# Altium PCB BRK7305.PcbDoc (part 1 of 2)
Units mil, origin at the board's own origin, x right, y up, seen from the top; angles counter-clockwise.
Board outline 4724.41 x 3149.61 mil, 4 copper layers (L1-TOP, L2-GND, L3-PWR, L4-BOT), stack 60.267 mil thick; 97 components, 177 nets, 610 pads, 294 vias.
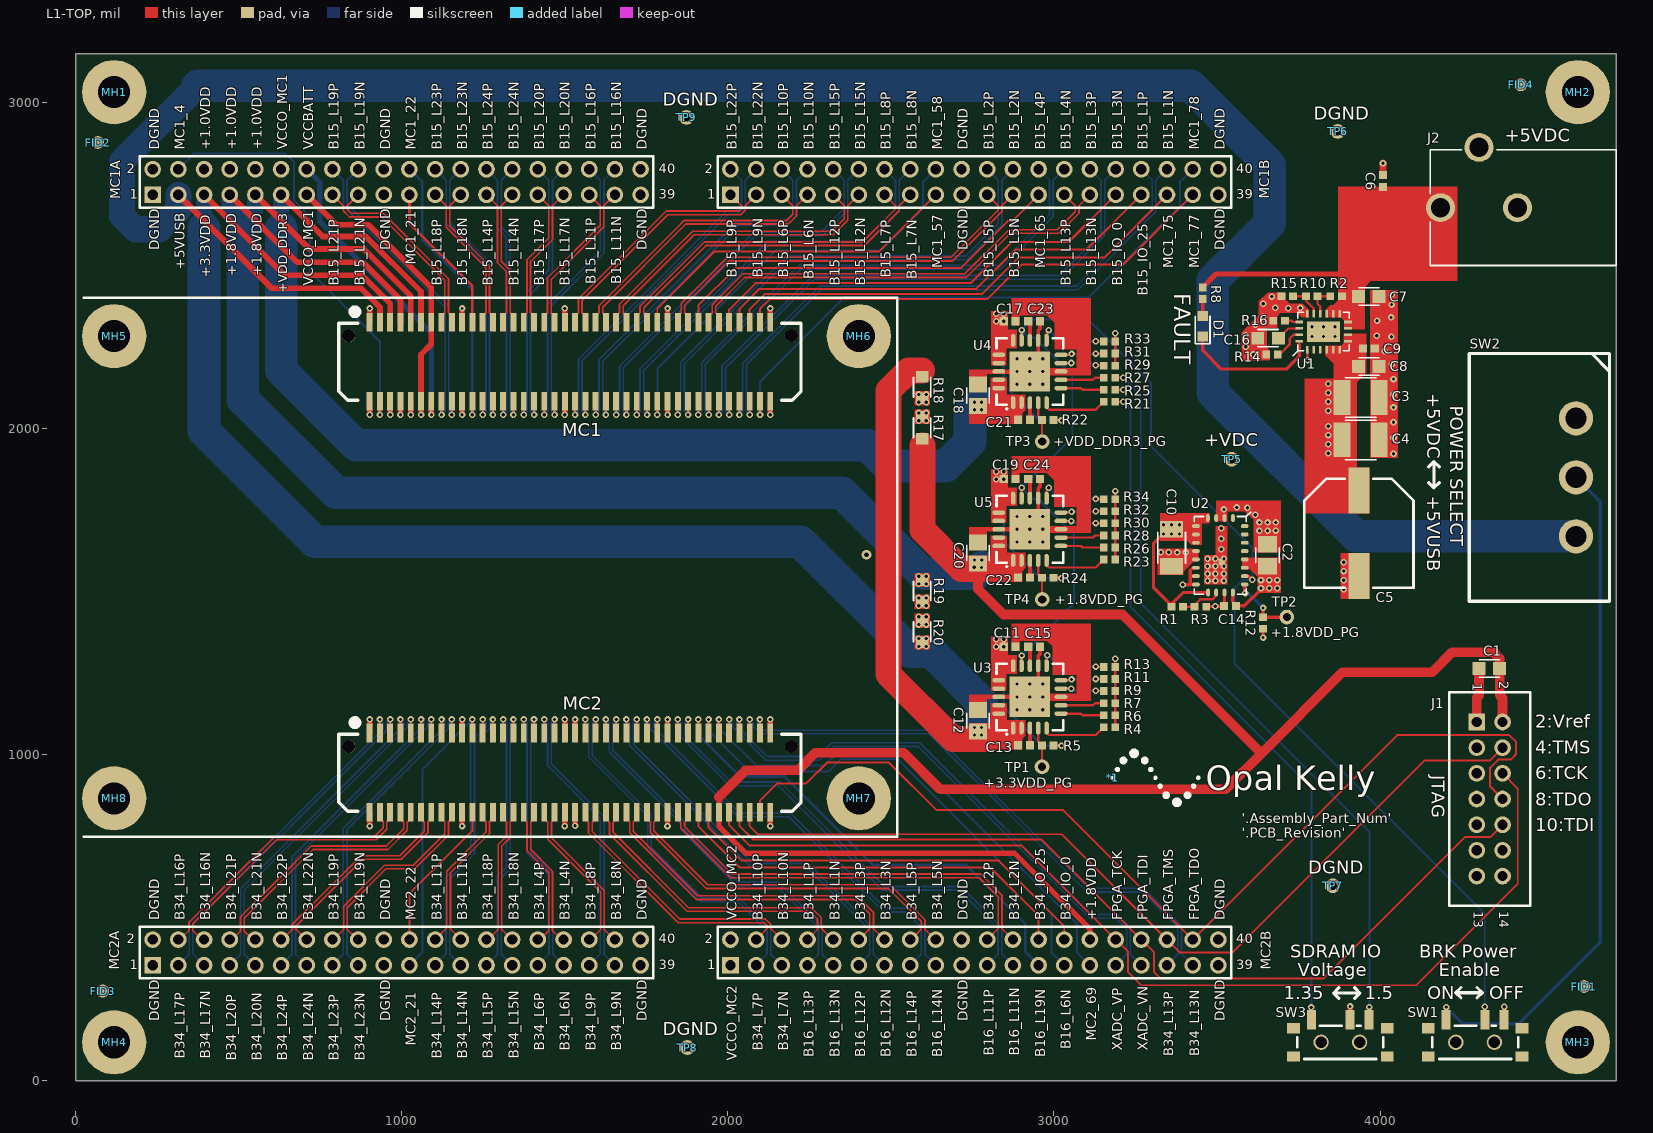
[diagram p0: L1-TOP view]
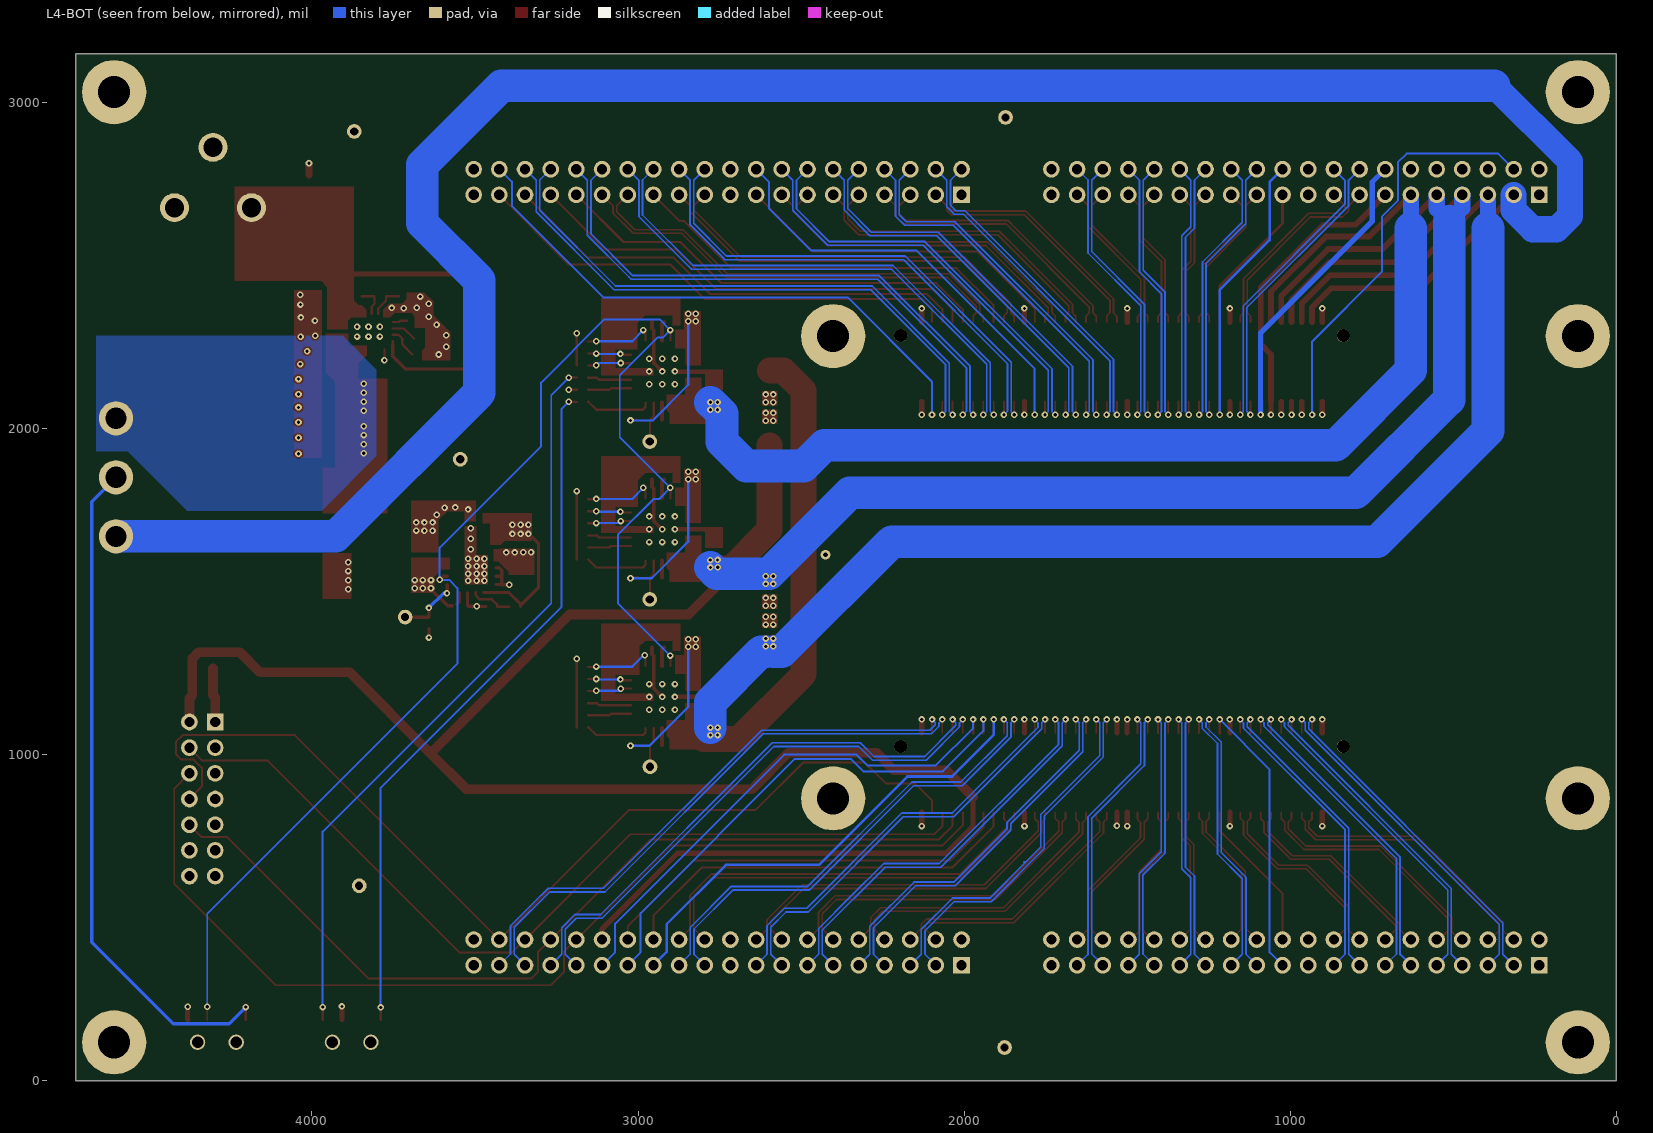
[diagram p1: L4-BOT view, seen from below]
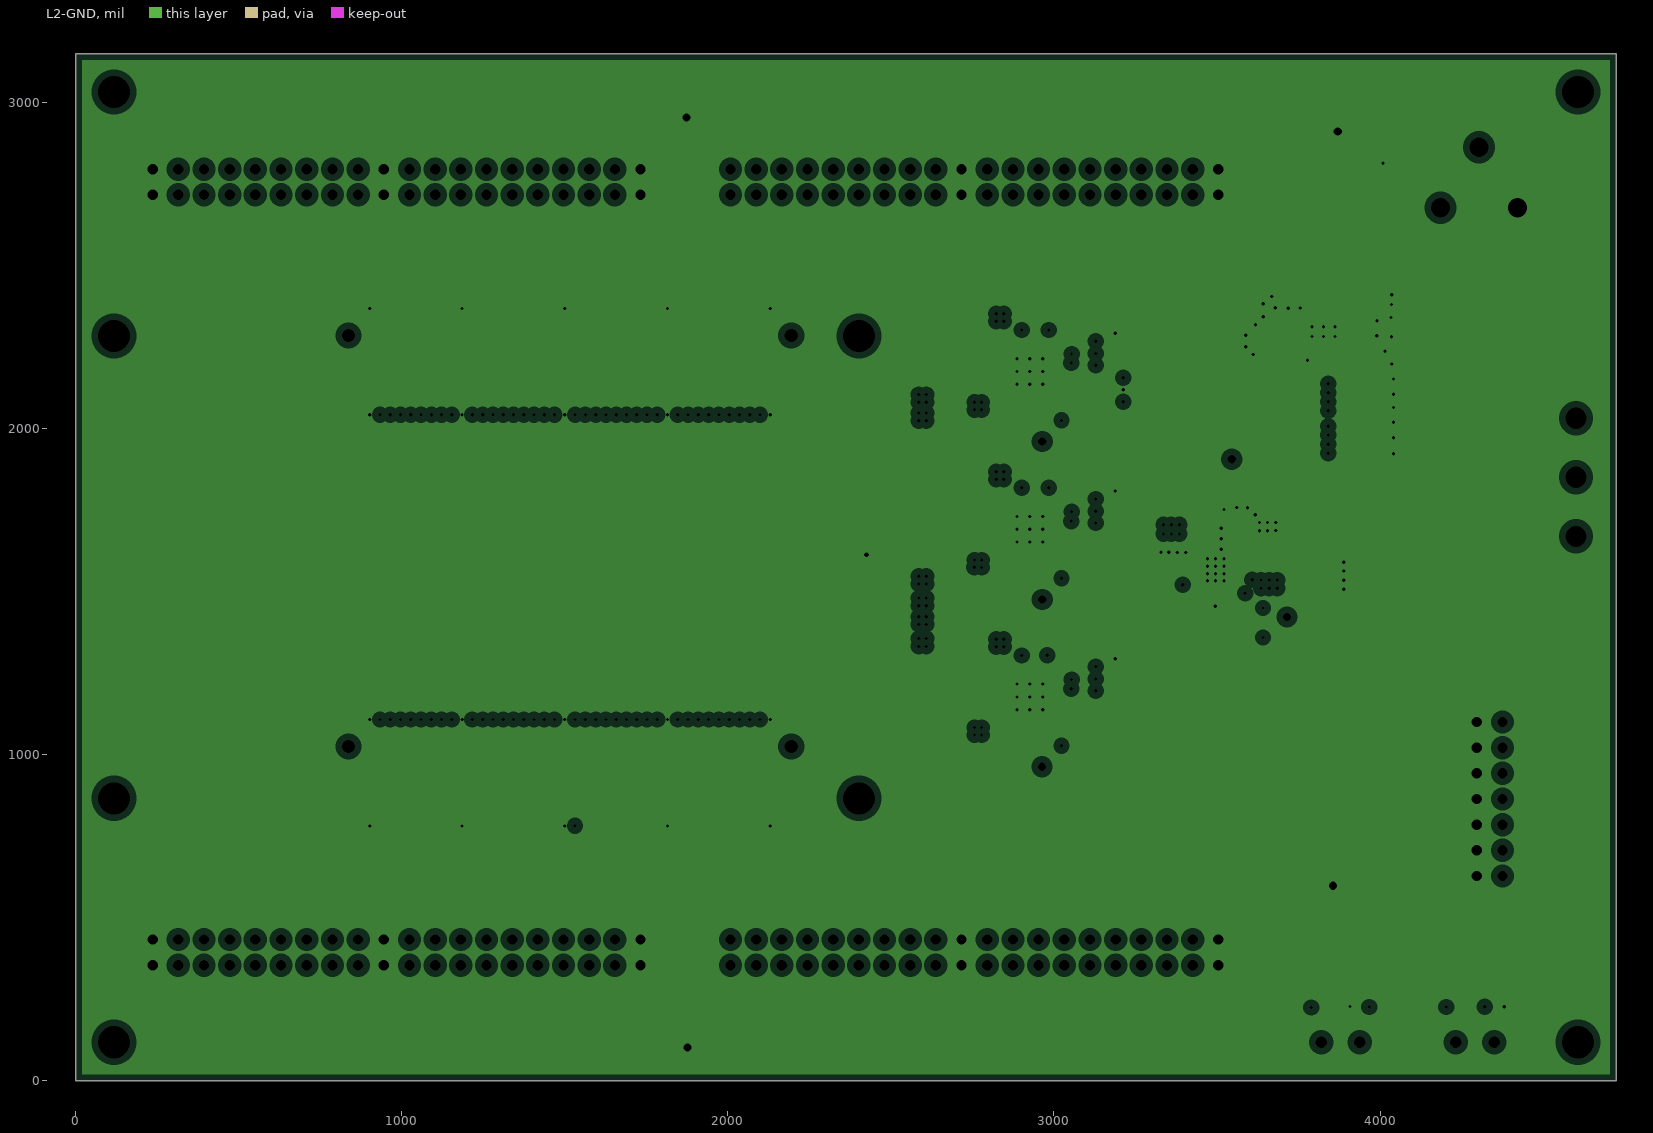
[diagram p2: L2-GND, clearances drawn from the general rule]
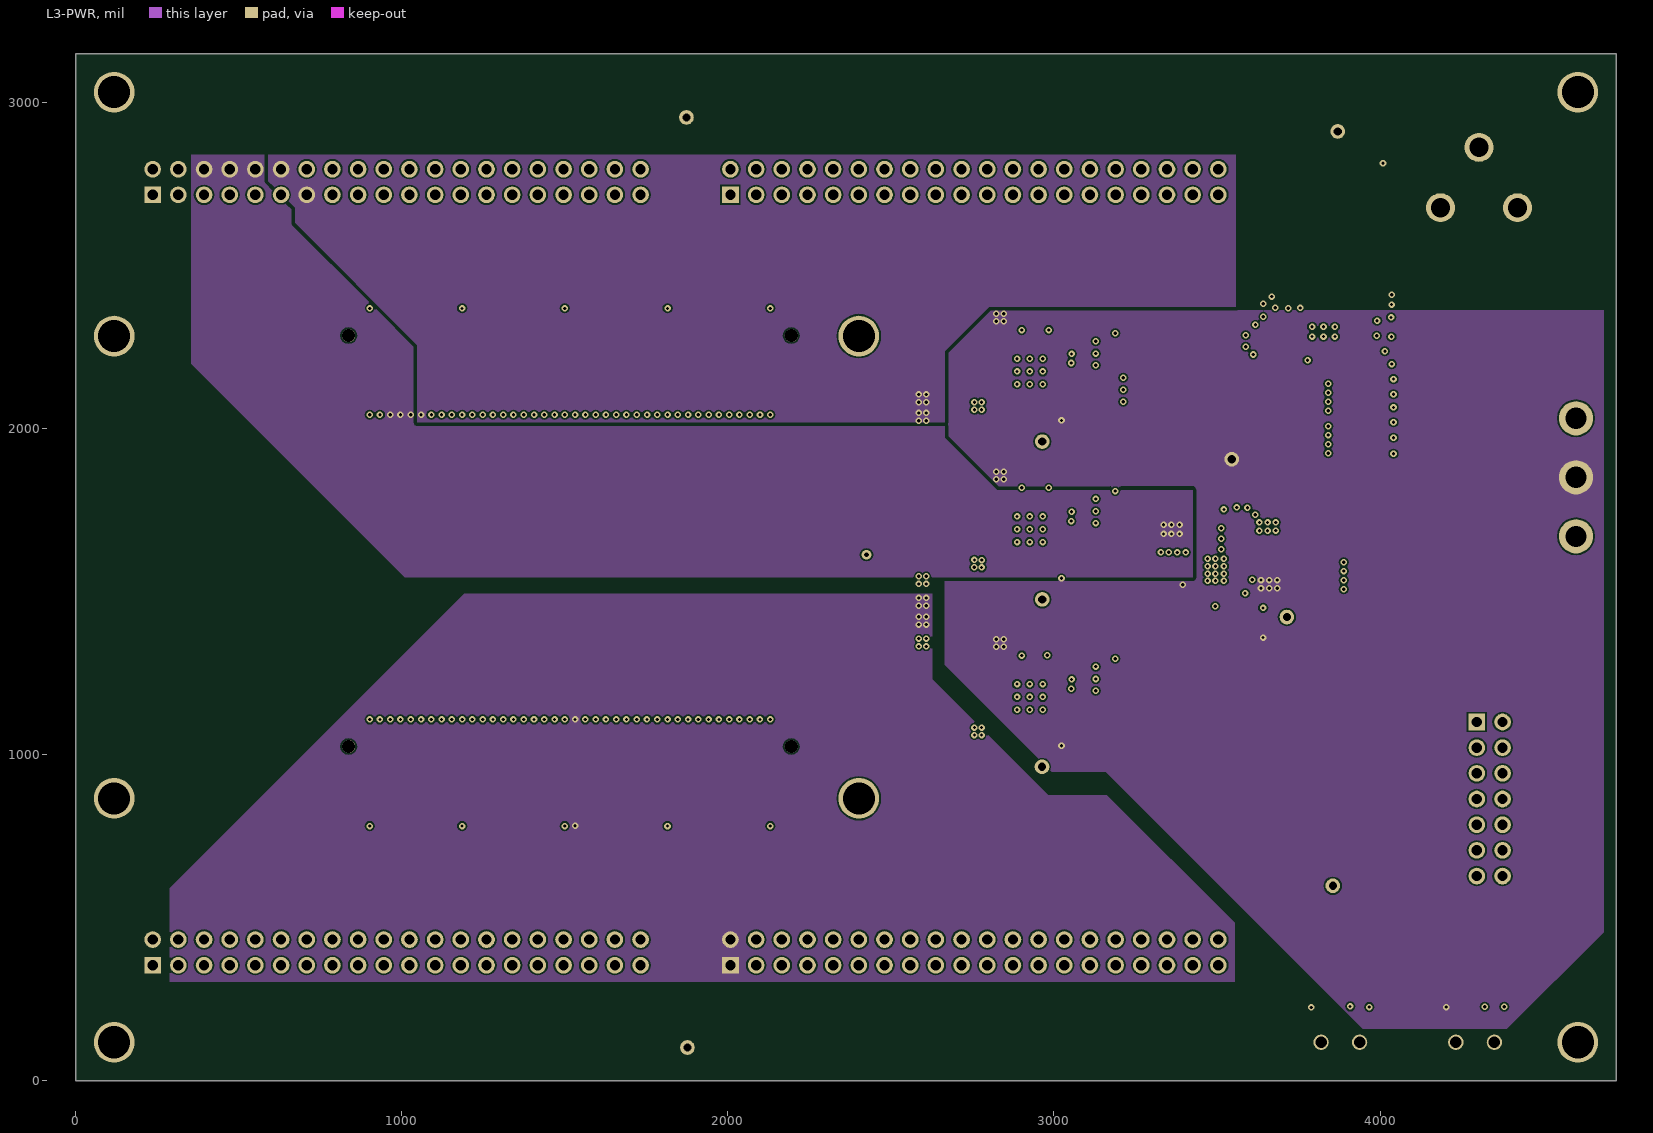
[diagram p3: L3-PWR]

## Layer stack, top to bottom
Top Solder: solder mask 0.4, Solder Resist, Dk 3.5
L1-TOP: signal copper 1.4
Dielectric1: prepreg 5.08, IT180A, Dk 4.2
L2-GND: plane copper 1.4, net DGND
Dielectric 2: core 44.49, IT180A, Dk 4.2
L3-PWR: signal copper 1.417
Dielectric 3: prepreg 5.08, IT180A, Dk 4.2
L4-BOT: signal copper 1.4
Bottom Solder: solder mask 0.4, Solder Resist, Dk 3.5

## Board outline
0,0 4724.41,0 4724.41,3149.61 0,3149.61

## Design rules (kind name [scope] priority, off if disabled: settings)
Clearance Fiducial [All vs ((Not PadIsPlated) And (HoleSize = 0))] p1: gap=25 ignorepadtopadclearanceinfootprint=FALSE except(0: Arc-Hole Track-Hole SMDPad-Hole THPad-Hole Via-Hole Fill-Hole Poly-Hole Region-Hole Text-Hole)
Clearance [All] p2: gap=5 ignorepadtopadclearanceinfootprint=FALSE except(0: Arc-Hole Track-Hole SMDPad-Hole THPad-Hole Via-Hole Fill-Hole Poly-Hole Region-Hole Text-Hole; 12: Fill-Fill Fill-Poly Fill-Region Poly-Poly Poly-Region Region-Region)
DiffPairsRouting okxDiffRouting100ohm [All] p1: maxlimit=10 minlimit=6 mostfreqgap=10 toplayer_maxgap=6 toplayer_prefgap=6 toplayer_minwidth=5.25 toplayer_maxwidth=5.25 toplayer_prefwidth=5.25 midlayer1_mingap=10 midlayer1_minwidth=15 midlayer1_maxwidth=15 midlayer1_prefwidth=15 bottomlayer_maxgap=6 bottomlayer_prefgap=6 bottomlayer_minwidth=5.25 bottomlayer_maxwidth=5.25 bottomlayer_prefwidth=5.25 maxuncoupledlength=500
FabricationTestPointUsage TestPointUsage [All] p1: valid=0 allowmultiple=FALSE
FabricationTestpoint Testpoint [All] p1: side=3 testpointundercomponent=TRUE minsize=40 maxsize=100 preferedsize=60 minholesize=0 maxholesize=40 preferedholesize=32 testpointgrid=1 allowsidetop=TRUE allowsidebottom=TRUE usegrid=TRUE gridtolerance=0.01
HoleSize [All] p1: absolutevalues=TRUE maxlimit=100 minlimit=8 maxpercent=80.000 minpercent=20.000
MinimumSolderMaskSliver [All] p1: minsoldermaskwidth=3
PlaneClearance [All] p1: clearance=20
PlaneConnect [All] p1: planeconnectstyle=Direct reliefexpansion=20 reliefentries=4 reliefconductorwidth=10 reliefairgap=10
PolygonConnect "Via Connect" [IsVia] p1: connectstyle=Direct reliefconductorwidth=10 reliefentries=4 polygonreliefangle="90 Angle" airgapwidth=10
PolygonConnect [All] p2: connectstyle=Direct reliefconductorwidth=10 reliefentries=4 polygonreliefangle="90 Angle" airgapwidth=10
RoutingVias [All] p1: holewidth=8 width=16 viastyle="Through Hole" minholewidth=8 minwidth=16 maxholewidth=25 maxwidth=50
SilkToSilkClearance [All] p1: silktosilkclearance=0.1
SilkToSolderMaskClearance [IsPad] p1: minsilkscreentomaskgap=2 clearancetoexposedcopper=TRUE
SolderMaskExpansion [All] p1: expansion=3
Width okWidth [All] p1: maxlimit=200 minlimit=5 preferedwidth=5 minimp=50.000000 maximp=50.000000 favimp=50.000000
21 further rules are at their usual default settings.

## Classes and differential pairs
differential pair DP_XADC: +XADC_VP -XADC_VN
differential pair DP_B34_L24: +B34_L24P -B34_L24N
differential pair DP_B34_L23: +B34_L23P -B34_L23N
differential pair DP_B34_L22: +B34_L22P -B34_L22N
differential pair DP_B34_L21: +B34_L21P -B34_L21N
differential pair DP_B34_L20: +B34_L20P -B34_L20N
differential pair DP_B34_L19: +B34_L19P -B34_L19N
differential pair DP_B34_L18: +B34_L18P -B34_L18N
differential pair DP_B34_L17: +B34_L17P -B34_L17N
differential pair DP_B34_L16: +B34_L16P -B34_L16N
differential pair DP_B34_L15: +B34_L15P -B34_L15N
differential pair DP_B34_L14: +B34_L14P -B34_L14N
differential pair DP_B34_L13_MRCC: +B34_L13P_MRCC -B34_L13N_MRCC
differential pair DP_B34_L11: +B34_L11P -B34_L11N
differential pair DP_B34_L10: +B34_L10P -B34_L10N
differential pair DP_B34_L9: +B34_L9P -B34_L9N
differential pair DP_B34_L8: +B34_L8P -B34_L8N
differential pair DP_B34_L7: +B34_L7P -B34_L7N
differential pair DP_B34_L6: +B34_L6P -B34_L6N
differential pair DP_B34_L5: +B34_L5P -B34_L5N
differential pair DP_B34_L4: +B34_L4P -B34_L4N
differential pair DP_B34_L3: +B34_L3P -B34_L3N
differential pair DP_B34_L2: +B34_L2P -B34_L2N
differential pair DP_B34_L1: +B34_L1P -B34_L1N
differential pair DP_B16_L14: +B16_L14P -B16_L14N
differential pair DP_B16_L13: +B16_L13P -B16_L13N
differential pair DP_B16_L12: +B16_L12P -B16_L12N
differential pair DP_B16_L11: +B16_L11P -B16_L11N
differential pair DP_B15_L24: +B15_L24P -B15_L24N
differential pair DP_B15_L23: +B15_L23P -B15_L23N
differential pair DP_B15_L22: +B15_L22P -B15_L22N
differential pair DP_B15_L21: +B15_L21P -B15_L21N
differential pair DP_B15_L20: +B15_L20P -B15_L20N
differential pair DP_B15_L19: +B15_L19P -B15_L19N
differential pair DP_B15_L18: +B15_L18P -B15_L18N
differential pair DP_B15_L17: +B15_L17P -B15_L17N
differential pair DP_B15_L16: +B15_L16P -B15_L16N
differential pair DP_B15_L15: +B15_L15P -B15_L15N
differential pair DP_B15_L14: +B15_L14P -B15_L14N
differential pair DP_B15_L13_MRCC: +B15_L13P_MRCC -B15_L13N_MRCC
differential pair DP_B15_L12_MRCC: +B15_L12P_MRCC -B15_L12N_MRCC
differential pair DP_B15_L11: +B15_L11P -B15_L11N
differential pair DP_B15_L10: +B15_L10P -B15_L10N
differential pair DP_B15_L9: +B15_L9P -B15_L9N
differential pair DP_B15_L8: +B15_L8P -B15_L8N
differential pair DP_B15_L7: +B15_L7P -B15_L7N
differential pair DP_B15_L6: +B15_L6P -B15_L6N
differential pair DP_B15_L5: +B15_L5P -B15_L5N
differential pair DP_B15_L4: +B15_L4P -B15_L4N
differential pair DP_B15_L3: +B15_L3P -B15_L3N
differential pair DP_B15_L2: +B15_L2P -B15_L2N
differential pair DP_B15_L1: +B15_L1P -B15_L1N

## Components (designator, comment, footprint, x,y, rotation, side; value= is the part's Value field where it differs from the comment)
*1 "Opal Kelly Logo" okLogo-23x5 3180,929 r0 top
C1 "C0603C104K4RACTU" CAPC1608N 4335,1264 r0 top value="0.1 u"
C2 "LMK212BJ106KG-T" CAPC2012N 3654.73,1611.44 r270 top locked value=10u
C3 "GRM32ER61C476KE15K" CAPC3225N 3940.41,2095.14 r0 top value="47 u"
C4 "GRM32ER61C476KE15K" CAPC3225N 3940.41,1965.14 r0 top value="47 u"
C5 "6SVPS220M" CAPAE9083X70N 3935,1679 r270 top value=220u
C6 "TMK105BJ104KV-F" CAPC1005X06N 4009,2759 r270 top value="0.1 u"
C7 "C0603C104K4RACTU" CAPC1608N 3965.41,2405.14 r180 top value="0.1 u"
C8 "C0603C104K4RACTU" CAPC1608N 3965.41,2190.14 r180 top value="0.1 u"
C9 "LMK105BJ105KV-F" CAPC1005X06N 3965.41,2245.14 r180 top value=1u
C10 "JMK316BJ476ML-T" CAPC3216N 3360.73,1634.44 r90 top locked value="47 u"
C11 "LMK105BJ105KV-F" CAPC1005X06N 2864,1331 r180 top value=1u
C12 "LMK212BJ106KG-T" CAPC2012X14N 2767,1104 r270 top value=10u
C13 "C0402C221J5GACTU" CAPC1005X06N 2908,1029 r180 top value="220 p"
C14 "LMK105BJ105KV-F" CAPC1005X06N 3539.73,1455.44 r0 top value=1u
C15 "C0402C103K4RACTU" CAPC1005X06N 2939,1331 r180 top value="0.01 u"
C16 "C0603C104K4RACTU" CAPC1608N 3656.41,2276.94 r0 top value="0.1 u"
C17 "LMK105BJ105KV-F" CAPC1005X06N 2864,2329 r180 top value=1u
C18 "LMK212BJ106KG-T" CAPC2012X14N 2767,2102 r270 top value=10u
C19 "LMK105BJ105KV-F" CAPC1005X06N 2864,1845.18 r180 top value=1u
C20 "LMK212BJ106KG-T" CAPC2012X14N 2767,1618.18 r270 top value=10u
C21 "C0402C221J5GACTU" CAPC1005X06N 2908,2027 r180 top value="220 p"
C22 "C0402C221J5GACTU" CAPC1005X06N 2908,1543.18 r180 top value="220 p"
C23 "C0402C103K4RACTU" CAPC1005X06N 2939,2329 r180 top value="0.01 u"
C24 "C0402C103K4RACTU" CAPC1005X06N 2939,1845.18 r180 top value="0.01 u"
D1 "FAULT" DIALIGHT-598-0603 3455.76,2313.49 r90 top
FID1 "FIDUCIAL" FID1MM/2MM-SS 4625,289 r90 top
FID2 "FIDUCIAL" FID1MM/2MM-SS 68,2877 r90 top
FID3 "FIDUCIAL" FID1MM/2MM-SS 83,275 r90 top
FID4 "FIDUCIAL" FID1MM/2MM-SS 4431,3054 r90 top
J1 "87831-1420" XILINX-JTAG 4336,864 r270 top
J2 "PJ-102AH" CUI-PJ102A 4724.41,2677.17 r90 top
MC1 "BTE-040-01-F-D-A" BTE-040 1515.75,2204.73 r0 top locked
MC1A "0877584016" HDR2X20-2MM 984.25,2755.91 r0 top locked
MC1B "0877584016" HDR2X20-2MM 2755.91,2755.91 r0 top locked
MC2 "BTE-040-01-F-D-A" BTE-040 1515.75,944.88 r0 top locked
MC2A "0877584016" HDR2X20-2MM 984.25,393.7 r0 top locked
MC2B "0877584016" HDR2X20-2MM 2755.91,393.7 r0 top locked
MH1 "MTG" MTG-2.5/5.0-PTH 118.11,3031.5 r0 top
MH2 "MTG" MTG-2.5/5.0-PTH 4606.3,3031.5 r0 top
MH3 "MTG" MTG-2.5/5.0-PTH 4606.3,118.11 r0 top
MH4 "MTG" MTG-2.5/5.0-PTH 118.11,118.11 r0 top
MH5 "MTG" MTG-2.5/5.0-PTH 118.11,2283.47 r0 top
MH6 "MTG" MTG-2.5/5.0-PTH 2401.58,2283.47 r0 top
MH7 "MTG" MTG-2.5/5.0-PTH 2401.58,866.14 r0 top
MH8 "MTG" MTG-2.5/5.0-PTH 118.11,866.14 r0 top
R1 "CRCW0402340KFKED" RESC1005X06N 3377.72,1454 r180 top value="340 k"
R2 "CRCW0402105KFKED" RESC1005X06N 3865.21,2405.84 r0 top value="105 k"
R3 "CRCW0402511KFKED" RESC1005X06N 3448.72,1454 r180 top value="511 k"
R4 "CRCW04020000Z0ED" RESC1005X06N 3170,1084 r180 top value=0
R5 "CRCW040210K0JNED" RESC1005X06N 2981,1028 r0 top value="10 k"
R6 "CRCW04020000Z0ED" RESC1005X06N 3170,1121 r180 top value=0
R7 "CRCW04020000Z0ED" RESC1005X06N 3170,1158 r180 top value=0
R8 "CRCW0402200RFKED" RESC1005X06N 3456,2415 r90 top value=200
R9 "CRCW04020000Z0ED" RESC1005X06N 3170,1195 r180 top value=0
R10 "CRCW040210K0JNED" RESC1005X06N 3790.21,2405.84 r0 top value="10 k"
R11 "CRCW04020000Z0ED" RESC1005X06N 3170,1232 r180 top value=0
R12 "CRCW040210K0JNED" RESC1005X06N 3641,1404 r270 top value="10 k"
R13 "CRCW04020000Z0ED" RESC1005X06N 3170,1269 r180 top value=0
R14 "CRCW040224K9FKED" RESC1005X06N 3668.41,2227.14 r0 top value="24.9 k"
R15 "CRCW040224K9FKED" RESC1005X06N 3715.21,2405.84 r0 top value="24.9 k"
R16 "CRCW040216K9FKED" RESC1005X06N 3690.41,2330.14 r0 top value="16.9 k"
R17 "CRCW06030000Z0EA" RESC1608N 2596,2002.54 r90 top value=0
R18 "CRCW06030000Z0EA" RESC1608N 2596,2126 r90 top value=0
R19 "CRCW06030000Z0EA" RESC1608N 2596,1502 r270 top value=0
R20 "CRCW06030000Z0EA" RESC1608N 2596,1377.54 r270 top value=0
R21 "CRCW04020000Z0ED" RESC1005X06N 3170,2082 r180 top value=0
R22 "CRCW040210K0JNED" RESC1005X06N 2981,2026 r0 top value="10 k"
R23 "CRCW04020000Z0ED" RESC1005X06N 3170,1598.18 r180 top value=0
R24 "CRCW040210K0JNED" RESC1005X06N 2981,1542.18 r0 top value="10 k"
R25 "CRCW04020000Z0ED" RESC1005X06N 3170,2119 r180 top value=0
R26 "CRCW04020000Z0ED" RESC1005X06N 3170,1635.18 r180 top value=0
R27 "CRCW04020000Z0ED" RESC1005X06N 3170,2156 r180 top value=0
R28 "CRCW04020000Z0ED" RESC1005X06N 3170,1672.18 r180 top value=0
R29 "CRCW04020000Z0ED" RESC1005X06N 3170,2193 r180 top value=0
R30 "CRCW04020000Z0ED" RESC1005X06N 3170,1709.18 r180 top value=0
R31 "CRCW04020000Z0ED" RESC1005X06N 3170,2230 r180 top value=0
R32 "CRCW04020000Z0ED" RESC1005X06N 3170,1746.18 r180 top value=0
R33 "CRCW04020000Z0ED" RESC1005X06N 3170,2267 r180 top value=0
R34 "CRCW04020000Z0ED" RESC1005X06N 3170,1783.18 r180 top value=0
SW1 "SSSS811101" SSSS811101 4291.34,118.11 r0 top
SW2 "L102011MS02Q" L102011MS 4488.19,1850.39 r180 top
SW3 "SSSS811101" SSSS811101 3877.95,118.11 r0 top
TP1 "+3.3VDD_PG" TP-PTH-25/45 2963.28,962.72 r180 top
TP2 "+1.8VDD_PG" TP-PTH-25/45 3714,1422 r270 top
TP3 "+VDD_DDR3_PG" TP-PTH-25/45 2964,1960 r90 top
TP4 "+1.8VDD_PG" TP-PTH-25/45 2964,1476.18 r180 top
TP5 "+VDC" TP-PTH-25/45 3545,1906 r90 top
TP6 "DGND" TP-PTH-25/45 3870,2911 r90 top
TP7 "DGND" TP-PTH-25/45 3855,598 r90 top
TP8 "DGND" TP-PTH-25/45 1876,102 r90 top
TP9 "DGND" TP-PTH-25/45 1873,2954 r90 top
U1 "TPS25940A" TPS25940 3826.41,2297.14 r0 top
U2 "EN5322" EN5322QI 3510.08,1611.44 r270 top
U3 "TPS7A7100RGWT" S-PVQN-N20 2926,1177 r90 top
U4 "TPS7A7100RGWT" S-PVQN-N20 2926,2175 r90 top
U5 "TPS7A7100RGWT" S-PVQN-N20 2926,1691.18 r90 top

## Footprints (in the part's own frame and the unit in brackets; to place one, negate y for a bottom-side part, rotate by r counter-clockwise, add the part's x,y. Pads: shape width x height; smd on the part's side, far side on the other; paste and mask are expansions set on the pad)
BTE-040 [mm] "0.8mm Samtech socket"
  rect 0.46x1.45 smd: 1(-15.6,3.085) 2(-15.6,-3.085) 3(-14.8,3.085) 4(-14.8,-3.085) 5(-14,3.085) 6(-14,-3.085) 7(-13.2,3.085) 8(-13.2,-3.085) 9(-12.4,3.085) 10(-12.4,-3.085) 11(-11.6,3.085) 12(-11.6,-3.085) 13(-10.8,3.085) 14(-10.8,-3.085) 15(-10,3.085) 16(-10,-3.085) 17(-9.2,3.085) 18(-9.2,-3.085) 19(-8.4,3.085) 20(-8.4,-3.085) 21(-7.6,3.085) 22(-7.6,-3.085) 23(-6.8,3.085) 24(-6.8,-3.085) 25(-6,3.085) 26(-6,-3.085) 27(-5.2,3.085) 28(-5.2,-3.085) 29(-4.4,3.085) 30(-4.4,-3.085) 31(-3.6,3.085) 32(-3.6,-3.085) 33(-2.8,3.085) 34(-2.8,-3.085) 35(-2,3.085) 36(-2,-3.085) 37(-1.2,3.085) 38(-1.2,-3.085) 39(-0.4,3.085) 40(-0.4,-3.085) 41(0.4,3.085) 42(0.4,-3.085) 43(1.2,3.085) 44(1.2,-3.085) 45(2,3.085) 46(2,-3.085) 47(2.8,3.085) 48(2.8,-3.085) 49(3.6,3.085) 50(3.6,-3.085) 51(4.4,3.085) 52(4.4,-3.085) 53(5.2,3.085) 54(5.2,-3.085) 55(6,3.085) 56(6,-3.085) 57(6.8,3.085) 58(6.8,-3.085) 59(7.6,3.085) 60(7.6,-3.085) 61(8.4,3.085) 62(8.4,-3.085) 63(9.2,3.085) 64(9.2,-3.085) 65(10,3.085) 66(10,-3.085) 67(10.8,3.085) 68(10.8,-3.085) 69(11.6,3.085) 70(11.6,-3.085) 71(12.4,3.085) 72(12.4,-3.085) 73(13.2,3.085) 74(13.2,-3.085) 75(14,3.085) 76(14,-3.085) 77(14.8,3.085) 78(14.8,-3.085) 79(15.6,3.085) 80(15.6,-3.085)
  round 1.02 hole 1.02: 81(-17.235,2.035) 82(17.235,2.035)
  silkscreen extent -18,-3 18,4.15
CAPAE9083X70N [mm] "Aluminum Electrolytic Capacitor, Body 8.30x8.30x7.00mm, IPC Medium Density"
  rect 3.6x1.65 smd: 1(-3.325,0) 2(3.325,0)
  silkscreen extent -4.25,-4.25 4.25,4.25, body extent -4.25,-4.25 4.25,4.25, height 7
CAPC1005X06N [mm] "Chip Capacitor, 2-Leads, Body 1.00x0.50mm, IPC Medium Density"
  rect 0.64x0.64 smd: 1(-0.46,0) 2(0.46,0)
  body extent -0.55,-0.3 0.55,0.3, height 0.6
CAPC1608N [mm] "Chip Capacitor, Body 1.6x0.8mm, IPC Medium Density"
  rect 1x1 smd: 1(-0.8,0) 2(0.8,0)
  silkscreen extent -0.8,-0.68 0.8,0.68, body extent -0.87,-0.48 0.87,0.48, height 0.85
CAPC2012N [mm] "Chip Capacitor, Body 2.0x1.3mm, IPC Medium Density"
  rect 1.3x1.5 smd: 1(-0.85,0) 2(0.85,0)
  silkscreen extent -0.6,-0.93 0.6,0.93, body extent -1.1,-0.72 1.1,0.72, height 1.1
CAPC2012X14N [mm] "Chip Capacitor, 2-Leads, Body 2.00x1.25mm, IPC Medium Density"
  rect 1.25x1.4 smd: 1(-0.825,0) 2(0.825,0)
  silkscreen extent -0.6,-0.88 0.6,0.88, body extent -1.05,-0.67 1.05,0.67, height 1.4
CAPC3216N [mm] "Chip Capacitor, Body 3.2x1.6mm, IPC Medium Density"
  rect 1.3x1.8 smd: 1(-1.45,0) 2(1.45,0)
  silkscreen extent -1.2,-1.08 1.2,1.08, body extent -1.7,-0.9 1.7,0.9, height 1.35
CAPC3225N [mm] "Chip Capacitor, Body 3.2x2.5mm, IPC Medium Density"
  rect 1.3x2.7 smd: 1(-1.45,0) 2(1.45,0)
  silkscreen extent -1.2,-1.53 1.2,1.53, body extent -1.7,-1.35 1.7,1.35, height 1.35
CUI-PJ102A [mm] "2.1mm/5.5mm DC power jack"
  round 2.25 hole 1.5: 1(0,13.7) 2(0,7.7) 3(4.7,10.7)
  silkscreen extent -4.5,0 4.5,14.5
DIALIGHT-598-0603 [mm] "Chip Diode; Body 1.6 x 0.8 mm (LxW typ)"
  rect 0.8x0.8 smd: 1(-0.8,0) 2(0.8,0)
  silkscreen extent -1.38,-0.58 0.8,0.58
EN5322QI [mm] "2A Voltage Mode Synchronous Buck PWM  DC-DC Converter"
  oval 0.6x0.3 smd mask+0.076: 1(-2.9,0.975) 2(-2.9,0.325) 3(-2.9,-0.325) 4(-2.9,-0.975) 13(2.9,-0.95) 14(2.9,-0.325) 15(2.9,0.325) 16(2.9,0.975)
  oval 0.3x0.6 smd mask+0.076: 5(-2.275,-1.9) 6(-1.625,-1.9) 7(-0.975,-1.9) 8(-0.325,-1.9) 9(0.325,-1.9) 10(0.975,-1.9) 11(1.625,-1.9) 12(2.275,-1.9) 17(2.275,1.9) 18(1.625,1.9) 19(0.975,1.9) 20(0.325,1.9) 21(-0.325,1.9) 22(-0.975,1.9) 23(-1.625,1.9) 24(-2.275,1.9)
  rect 0.5x0.5 smd paste-1.5 mask+0.076: PAD(0.525,0.1)
  L1-TOP region: -2.25,0.55 2.25,0.55 2.25,-1.25 0,-1.25 0,-0.35 -2.25,-0.35
  silkscreen extent -3.39,-2.02 3.02,2.39
FID1MM/2MM-SS [mm] "Fiducial 1mm copper, 2mm soldermask, single-side"
  round 1 smd paste-0.5 mask+0.5: FID?(0,0)
HDR2X20-2MM [mm] "2mm 2x20 header"
  rect 1.3x1.3 hole 0.8: 1(-19,-1)
  round 1.3 hole 0.8: 2(-19,1) 3(-17,-1) 4(-17,1) 5(-15,-1) 6(-15,1) 7(-13,-1) 8(-13,1) 9(-11,-1) 10(-11,1) 11(-9,-1) 12(-9,1) 13(-7,-1) 14(-7,1) 15(-5,-1) 16(-5,1) 17(-3,-1) 18(-3,1) 19(-1,-1) 20(-1,1) 21(1,-1) 22(1,1) 23(3,-1) 24(3,1) 25(5,-1) 26(5,1) 27(7,-1) 28(7,1) 29(9,-1) 30(9,1) 31(11,-1) 32(11,1) 33(13,-1) 34(13,1) 35(15,-1) 36(15,1) 37(17,-1) 38(17,1) 39(19,-1) 40(19,1)
  silkscreen extent -20,-2 20,2
L102011MS [mil]
  round 105 hole 65: 1(-112.5,-181) 2(-112.5,0) 3(-112.5,181)
  silkscreen extent -215,-380 215,380
MTG-2.5/5.0-PTH [mm] "Mounting hole, 2.5mm ID, 5.0mm OD, plated"
  round 5 / inner round 3.175 / far side round 5 hole 2.5: 1(0,0)
okLogo-23x5 [mil] "Opal Kelly silkscreen logo (23mm x 5mm)"
  silkscreen extent -3,-82 266,82
RESC1005X06N [mm] "Chip Resistor, 2-Leads, Body 1.00x0.50mm, IPC Medium Density"
  rect 0.6x0.6 smd: 1(-0.45,0) 2(0.45,0)
  body extent -0.55,-0.3 0.55,0.3, height 0.6
RESC1608N [mm] "Chip Resistor, Body 1.6x0.8mm, IPC Medium Density"
  rect 0.9x1 smd: 1(-0.85,0) 2(0.85,0)
  silkscreen extent -0.77,-0.68 0.78,0.68, body extent -0.85,-0.48 0.85,0.48, height 0.6
S-PVQN-N20 [mm]
  rect 3.15x3.15 smd paste-4: 0(0,0)
  rrect100% 1x0.35 smd mask+0.07: 1(-2.425,1.3) 2(-2.425,0.65) 3(-2.425,0) 4(-2.425,-0.65) 5(-2.425,-1.3) 11(2.425,-1.3) 12(2.425,-0.65) 13(2.425,0) 14(2.425,0.65) 15(2.425,1.3)
  rrect100% 0.35x1 smd mask+0.07: 6(-1.3,-2.425) 7(-0.65,-2.425) 8(0,-2.425) 9(0.65,-2.425) 10(1.3,-2.425) 16(1.3,2.425) 17(0.65,2.425) 18(0,2.425) 19(-0.65,2.425) 20(-1.3,2.425)
  silkscreen extent -2.9,-2.6 2.6,2.6
SSSS811101 [mm] "Surface mount, 1 position, 2 pole switch"
  rect 1x0.8 smd: 0(-3.65,-1.1) 0(-3.65,1.1) 0(3.65,-1.1) 0(3.65,1.1)
  round 1.2 hole 0.9: 0(-1.5,0) 0(1.5,0)
  rect 0.7x1.5 smd: 1(-2.25,1.75) 2(0.75,1.75) 3(2.25,1.75)
  silkscreen extent -3.35,-1.3 3.35,1.3
TP-PTH-25/45 [mil] "Test point, plated through-hole, 25/45mil"
  round 45 hole 25: 1(0,0)
TPS25940 [mm] "QFN, 20-Leads, Body 3x4mm, Pitch 0.5mm"
  rect 0.2x0.6 smd: 1(-1.25,-1.4) 2(-0.75,-1.4) 3(-0.25,-1.4) 4(0.25,-1.4) 5(0.75,-1.4) 6(1.25,-1.4) 11(1.25,1.4) 12(0.75,1.4) 13(0.25,1.4) 14(-0.25,1.4) 15(-0.75,1.4) 16(-1.25,1.4)
  rect 0.6x0.2 smd: 7(1.9,-0.75) 8(1.9,-0.25) 9(1.9,0.25) 10(1.9,0.75) 17(-1.9,0.75) 18(-1.9,0.25) 19(-1.9,-0.25) 20(-1.9,-0.75)
  rect 2.6x1.6 smd paste-3: PAD(0,0)
  silkscreen extent -2.38,-1.88 2,1.5, body extent -2,-1.5 2,1.5, height 0.8
XILINX-JTAG [mm] "2mm 2x7 header"
  rect 1.3x1.3 hole 0.8: 1(-6,-1)
  round 1.3 hole 0.8: 2(-6,1) 3(-4,-1) 4(-4,1) 5(-2,-1) 6(-2,1) 7(0,-1) 8(0,1) 9(2,-1) 10(2,1) 11(4,-1) 12(4,1) 13(6,-1) 14(6,1)
  silkscreen extent -8.32,-3.15 8.32,3.15

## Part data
*1: library part OKLOGO
C1 C7 C8 C16: library part 000019, "Ceramic capacitor", Manufacturer=Kemet, ValueFloat=1E-7
C2: library part 000491, "Ceramic capacitor", Manufacturer="Taiyo Yuden", Tolerance (%)=10, ValueFloat=1E-5, Voltage=10V
C3 C4: library part 001368, "Ceramic Capacitor", Manufacturer=Murata, Tolerance (%)=10, ValueFloat=4.7E-5, Voltage=16V, x_voltage-rating=16
C5: library part 001384, "Capacitor, Solid Polymer Aluminum, 220uF, 6.3V, 8mm dia, 22mOhm", Manufacturer=Panasonic, Tolerance (%)=20, ValueFloat=0.00022, Voltage=6.3V, x_voltage-rating=6.3
C6: library part 001073, "Ceramic capacitor", Manufacturer="Taiyo Yuden", Tolerance (%)=10, ValueFloat=1E-7, Voltage=25V
C9 C11 C14 C17 C19: library part 000480, "Ceramic capacitor", Manufacturer="Taiyo Yuden", Tolerance (%)=10, ValueFloat=1E-6
C10: library part 000570, "Ceramic Capacitor", Manufacturer="Taiyo Yuden", Tolerance (%)=20, ValueFloat=4.7E-5, Voltage=6.3V
C12 C18 C20: library part 000491, "Ceramic capacitor", Manufacturer="Taiyo Yuden", Tolerance (%)=10, ValueFloat=1E-5
C13 C21 C22: library part 001219, "Ceramic capacitor", Manufacturer=Kemet, Tolerance (%)=5, ValueFloat=2.2E-10
C15 C23 C24: library part 000295, "Ceramic Capacitor", Manufacturer=Kemet, Tolerance (%)=10, ValueFloat=1E-8
D1: library part 001432, "LED", Manufacturer=Dialight, Manufacturer_PN=598-8010-107F
FID1 FID2 FID3 FID4: "PCB fiducial"
J1: library part 000541, "2mm header, shrouded", Manufacturer=Molex
J2: library part 000356, "DC power connector - high current", Manufacturer="CUI Inc."
MC1 MC2: library part 000059, "0.8mm high-density header", Manufacturer=Samtec
MC1A MC1B MC2A MC2B: library part 000583, "2mm header, 20x2, thru-hole", Manufacturer=Molex
MH1 MH2 MH3 MH4 MH5 MH6 MH7 MH8: "Mounting hole"
R1: library part 001234, "Thick-film resistor", Manufacturer=Vishay, Tolerance (%)=1, ValueFloat=340000
R2: library part 001124, "Thick-film resistor", Manufacturer=Vishay, Tolerance (%)=1, ValueFloat=105000
R3: library part 001409, "Thick-film resistor", Manufacturer=Vishay, Tolerance (%)=1, ValueFloat=511000
R4 R6 R7 R9 R11 R13 R21 R23 R25 R26 R27 R28 R29 R30 R31 R32 R33 R34: library part 000755, "Thick-film resistor", Manufacturer=Vishay, Tolerance (%)=1, ValueFloat=0
R5 R10 R12 R22 R24: library part 000759, "Thick-film resistor", Manufacturer=Vishay, Tolerance (%)=5, ValueFloat=10000
R8: library part 000780, "Thick-film resistor", Manufacturer=Vishay, Tolerance (%)=1, ValueFloat=200
R14 R15: library part 000934, "Thick-film resistor", Manufacturer=Vishay, Tolerance (%)=1, ValueFloat=24900
R16: library part 001332, "Thick-film resistor", Manufacturer=Vishay, Tolerance (%)=1, ValueFloat=16900
R17 R18 R19 R20: library part 000411, "Zero-ohm resistor", Manufacturer=Vishay, ValueFloat=0
SW1 SW3: library part 000231, "Slide", Manufacturer=Alps
SW2: library part 001220, "SPDT", Manufacturer="C&K Components"
TP1 TP2 TP3 TP4 TP5 TP6 TP7 TP8 TP9: library part TP-PTH-25/45, "Test point, plated through-hole, 25/45mil"
U1: library part 001325, "18V eFuse with reverse- /over-voltage protection and current limiting, auto-retry", Manufacturer="Texas Instruments"
U2: library part 000477, "2A Synchronous Buck DC-DC converter", Manufacturer=Altera, Manufacturer_PN=EN5322QI
U3 U4 U5: library part 001209, "LDO voltage regulator", Manufacturer="Texas Instruments"

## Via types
v1: diameter 20, hole 10, L1-TOP to L4-BOT, tented both sides, 293 vias
v2: diameter 30, hole 15, L1-TOP to L4-BOT, tented both sides, 1 vias

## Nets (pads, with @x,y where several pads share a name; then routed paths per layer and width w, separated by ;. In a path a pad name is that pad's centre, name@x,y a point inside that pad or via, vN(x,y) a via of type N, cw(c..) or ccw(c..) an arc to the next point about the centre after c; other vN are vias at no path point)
+1.0VDD: C10.2 MC1.6 MC1.8 MC1.10 MC1A.6 MC1A.8 MC1A.10 R1.2 U2.4 U2.5 U2.6 U2.7 U2.13 | length 548.5
  L1-TOP w10: C10.2@3360.73,1691.53 3349.53,1691.53 3305,1647 3305,1513 3360,1458 R1.2@3360,1454 3360,1461 3396.27,1497.27 U2.13@3472.68,1497.27
  L1-TOP w16: v1(964.57,2042) MC1.6@964.57,2083.27 ; v1(996.06,2042) MC1.8@996.06,2083.27 ; v1(1027.56,2042) MC1.10@1027.56,2083.27
  other v1: 3336,1677 3360,1677 3385,1677 3336,1705 3360,1705 3385,1705
+1.8VDD: C1.2 C20.2 C22.2 J1.2 MC1.7 MC1.9 MC1A.7 MC1A.9 MC2.70 MC2B.30 R17.1 R19.1 U5.1 U5.2 U5.19 U5.20 | length 10535.7
  L1-TOP w16: 1972.44,870.44 MC2.70@1972.44,823.43 1972.44,779.56 2054,698 2878,698 3110.24,465.76 MC2B.30@3110.24,433.07
  L1-TOP w18: MC1A.7@472.44,2716.54 678.98,2510 881,2510 996.06,2394.94 MC1.7@996.06,2326.18 ; MC1A.9@551.18,2716.54 717.72,2550 884,2550 1027.56,2406.44 MC1.9@1027.56,2326.18
  L1-TOP w30: 1972.44,870.44 2054,952 2215,952 2269,1006 2539,1006 2651,894 3526,894 3636,1004 ; C20.2@2767,1585.7 2767,1508 2845,1430 3210,1430 3636,1004 ; J1.2@4375.37,1100.22 4375.37,1173.13 4366.5,1182 C1.2@4366.5,1264 4366.5,1294.5 4347,1314 4221,1314 4160,1253 3885,1253 3636,1004
  L1-TOP w80: 2597,1948 2597,1689 2716,1570 C20.2@2755.5,1570
  L4-BOT w50: MC1A.7@472.44,2716.54 472.44,2676.56 513,2636 551.18,2674.18 MC1A.9@551.18,2716.54
  L4-BOT w100: 513,2636 513,2089 799,1803 2350,1803 2598,1555 2758.8,1555 v1(2778,1574.2)
  other v1: 2585,1523.39 2608,1523.39 2585,1547.39 2608,1547.39 2755.5,1574.7 2756,1597.2 2778.5,1596.7
+3.3VDD: C12.2 C13.2 MC1.5 MC1A.5 R18.2 R20.2 U3.1 U3.2 U3.19 U3.20 | length 5697.2
  L1-TOP w18: MC1A.5@393.7,2716.54 640.24,2470 878,2470 964.57,2383.43 MC1.5@964.57,2326.18
  L1-TOP w80: 2595,2178 2554,2178 2492,2116 2492,1247 2691,1048 2799,1048
  L4-BOT w50: 393.7,2578 MC1A.5@393.7,2716.54
  L4-BOT w100: 393.7,2614 393.7,1993.3 734,1653 2222,1653 2559,1316 2585,1316 ; 2607,1316 2622.54,1316 2778,1160.54 v1(2778,1083.02)
  other v1: 2756,1060.02 2778,1060.02 2756,1083.02 2585,1332 2608,1332 2585,1356 2608,1356
+5VDC: C3.1 C4.1 C5.1 C8.2 C9.2 SW2.1 U1.4 U1.5 U1.6 U1.7 U1.8
  other v1: 3840.71,1924.54 3840.71,1952 3840.71,1980 3840.71,2007 3840.71,2054.54 3840.71,2082 3840.71,2110 3840.71,2137
+5VUSB: MC1.3 MC1A.3 SW2.3 | length 7017.3
  L1-TOP w18: MC1A.3@314.96,2716.54 601.5,2430 875,2430 933.07,2371.93 MC1.3@933.07,2326.18
  L4-BOT w80: MC1A.3@314.96,2716.54 314.96,2669.61 256.35,2611 183,2611 142,2652 142,2819 374,3051
  L4-BOT w100: 374,3051 3419,3051 3661,2809 3661,2629 3487,2455 3487,2110 3927.61,1669.39 SW2.3@4600.69,1669.39
+VDC: C2.2 C11.2 C14.2 C17.2 C19.2 R5.2 R12.2 R22.2 R24.2 SW1.1 SW2.2 TP5.1 U2.10 U2.11 U2.12 U2.16 U2.19 U2.20 U3.15 U3.16 U3.17 U4.15 U4.16 U4.17 U5.15 U5.16 U5.17 | length 3685.6
  L1-TOP w7: R5.2@2998.72,1028 3022,1028 v1(3023,1027) ; R24.2@2998.72,1542.18 3022,1542.18 v1(3023,1541.18) ; R22.2@2998.72,2026 3022,2026 v1(3023,2025)
  L1-TOP w8: SW1.1@4203,187.25 v1(4203,226)
  L1-TOP w10: v1(3395,1521) 3418,1521 3418,1547 ; 3418,1521.87 U2.12@3435.28,1521.87 ; U2.11@3435.28,1547.46 3418.46,1547.46 3418,1547 ; U2.10@3435.28,1573.06 3425.06,1573.06 3418,1566 3418,1547 ; U2.16@3548.46,1497.27 3548.46,1468.71 C14.2@3556.73,1460.44 ; C14.2@3569.73,1456.44 3583.58,1456.44 v1@3635,1507.86 ; v1(3641,1359) R12.2@3641,1386.28
  L4-BOT w7: v1(2845.89,1330.63) 2845.89,1146.11 2965,1027 v1(3023,1027) ; v1(2845.89,1844.81) 2845.89,1653.29 2958,1541.18 v1(3023,1541.18) ; v1(2845.89,2328.63) 2845.89,2134.11 2955,2025 v1(3023,2025)
  L4-BOT w10: v1(4203,226) 4254,175 4425,175 4675,425 4675,1776.08 SW2.2@4600.69,1850.39
  other v1: 2823,1330.63 2823,1353.63 2846,1353.63 3634.73,1510.44 3659.73,1510.44 3684.73,1510.44 3634.73,1535.44 3659.73,1535.44 3684.73,1535.44 2823,1844.81 2823,1867.81 2846,1867.81 2823,2328.63 2823,2351.63 2846,2351.63
+VDCIN: C6.2 C7.2 J2.1 R2.2 R8.2 U1.9 U1.10 U1.11 U1.12 U1.13 | length 522.3
  L1-TOP w7: R2.2@3883.12,2398.14 R2.2@3883.12,2405.84
  L1-TOP w10: C7.2@3933.01,2404.24 C7.2@3933.91,2405.14
  L1-TOP w16: R8.2@3456.21,2433.29 3496.4,2473.49 3882.76,2473.49 3888.83,2467.42 R2.2@3888.83,2405.84
+VDD_DDR3: C18.2 C21.2 MC1.11 MC1A.11 U4.1 U4.2 U4.19 U4.20 | length 3560.1
  L1-TOP w18: MC1A.11@629.92,2716.54 757.46,2589 890,2589 1059.06,2419.94 MC1.11@1059.06,2326.18
  L4-BOT w50: 629.92,2638.53 MC1A.11@629.92,2716.54
  L4-BOT w100: 630,2614 629.92,2179.08 860,1949 2428,1949 2492,1885 2668,1885 2742.49,1959.49 2742.49,2045.51 v1(2778,2081.02)
  other v1: 2756,2058.02 2778,2058.02 2756,2081.02
B15_IO_0: MC1.71 MC1B.31 | length 1369.4
  L1-TOP w6: MC1.71@2003.94,2326.18 2003.94,2364.94 2085,2446 2744,2446 2870,2572 3044.44,2572 MC1B.31@3188.98,2716.54
B15_IO_25: MC1.73 MC1B.33 | length 1417.6
  L1-TOP w6: MC1.73@2035.43,2326.18 2035.43,2366.43 2097,2428 2762,2428 2883,2549 3100.18,2549 MC1B.33@3267.72,2716.54
B15_L1N: MC1.76 MC1B.36 | length 1793.9
  L1-TOP w5.25: MC1.76@2066.93,2083.27 2066.93,2042.07 v1(2067,2042)
  L4-BOT w5.25: v1(2067,2042) 2056.88,2052.12 2056.88,2195.97 2286.66,2425.75 3073.66,2425.75 3075.91,2428 3312.25,2664.34 3312.25,2761.07 MC1B.36@3346.46,2795.28
B15_L1P: MC1.74 MC1B.34 | length 1793.6
  L1-TOP w5.25: MC1.74@2035.43,2083.27 2035.43,2042.07 v1(2035.5,2042)
  L4-BOT w5.25: v1(2035.5,2042) 2045.63,2052.12 2045.63,2200.63 2282,2437 3069,2437 3301,2669 3301,2761.99 MC1B.34@3267.72,2795.28
B15_L2N: MC1.64 MC1B.24 | length 1537.3
  L1-TOP w5.25: MC1.64@1877.95,2083.27 1877.95,2042.07 v1(1878.02,2042)
  L4-BOT w5.25: v1(1878.02,2042) 1867,2053.02 1867,2199.09 2185.66,2517.75 2733.66,2517.75 2740.66,2524.75 2840.27,2624.36 2840.27,2761.53 MC1B.24@2874.02,2795.28
B15_L2P: MC1.62 MC1B.22 | length 1536.5
  L1-TOP w5.25: MC1.62@1846.46,2083.27 1846.46,2042.07 v1(1846.53,2042)
  L4-BOT w5.25: v1(1846.53,2042) 1855.75,2051.22 1855.75,2203.75 2181,2529 2729,2529 2829.02,2629.02 2829.02,2761.53 MC1B.22@2795.28,2795.28
B15_L3N: MC1.72 MC1B.32 | length 1737.3
  L1-TOP w5.25: MC1.72@2003.94,2083.27 2003.94,2042.07 v1(2004.01,2042)
  L4-BOT w5.25: v1(2004.01,2042) 1993,2053.01 1993,2186 2264.75,2457.75 3020.66,2457.75 3027.66,2464.75 3155.23,2592.32 3155.23,2761.53 MC1B.32@3188.98,2795.28
B15_L3P: MC1.70 MC1B.30 | length 1736.6
  L1-TOP w5.25: v1(1972.44,2042) MC1.70@1972.44,2083.27
  L4-BOT w5.25: v1(1972.44,2042) 1981.75,2051.31 1981.75,2190.66 2260.09,2469 3016,2469 3143.98,2596.98 3143.98,2761.53 MC1B.30@3110.24,2795.28
B15_L4N: MC1.68 MC1B.28 | length 1613.7
  L1-TOP w5.25: MC1.68@1940.95,2083.27 1940.95,2042.07 v1(1941.02,2042)
  L4-BOT w5.25: v1(1941.02,2042) 1930.89,2052.12 1930.89,2196.98 2222.66,2488.75 2835.66,2488.75 2843.91,2497 2997.25,2650.34 2997.25,2761.03 MC1B.28@3031.5,2795.28
B15_L4P: MC1.66 MC1B.26 | length 1613.3
  L1-TOP w5.25: MC1.66@1909.45,2083.27 1909.45,2042.07 v1(1909.52,2042)
  L4-BOT w5.25: v1(1909.52,2042) 1919.64,2052.12 1919.64,2201.64 2218,2500 2831,2500 2986,2655 2986,2762.03 MC1B.26@2952.76,2795.28
B15_L5N: MC1.63 MC1B.23 | length 1213
  L1-TOP w5.25: MC1.63@1877.95,2326.18 1877.95,2345.05 1868,2355 1868,2379 2003,2514 2689,2514 2840.27,2665.27 2840.27,2682.79 MC1B.23@2874.02,2716.54
B15_L5P: MC1.61 MC1B.21 | length 1213.2
  L1-TOP w5.25: MC1.61@1846.46,2326.18 1846.46,2344.71 1856.75,2355 1856.75,2383.66 1925.09,2452 1998.34,2525.25 2684.34,2525.25 2829.02,2669.93 2829.02,2682.79 MC1B.21@2795.28,2716.54
B15_L6N: MC1.47 MC1B.7 | length 838.5
  L1-TOP w5.25: MC1.47@1625.98,2326.18 1625.98,2345.02 1616,2355 1616,2372 1871,2627 2184.91,2627 2210.35,2652.44 2210.35,2682.79 MC1B.7@2244.1,2716.54
B15_L6P: MC1.45 MC1B.5 | length 838.7
  L1-TOP w5.25: MC1.45@1594.49,2326.18 1594.49,2344.74 1604.75,2355 1604.75,2376.66 1840.09,2612 1866.34,2638.25 2180.25,2638.25 2199.1,2657.1 2199.1,2682.79 MC1B.5@2165.35,2716.54
B15_L7N: MC1.55 MC1B.15 | length 1017
  L1-TOP w5.25: MC1.55@1751.97,2326.18 1751.97,2345.03 1742,2355 1742,2370 1933,2561 2417.97,2561 2525.31,2668.34 2525.31,2682.79 MC1B.15@2559.06,2716.54
B15_L7P: MC1.53 MC1B.13 | length 1017.1
  L1-TOP w5.25: MC1.53@1720.47,2326.18 1720.47,2344.72 1730.75,2355 1730.75,2374.66 1847.09,2491 1928.34,2572.25 2413.31,2572.25 2514.06,2673 2514.06,2682.79 MC1B.13@2480.32,2716.54
B15_L8N: MC1.56 MC1B.16 | length 1308.9
  L1-TOP w5.25: MC1.56@1751.97,2083.27 1751.97,2042.07 v1(1752.04,2042)
  L4-BOT w5.25: v1(1752.04,2042) 1741.92,2052.12 1741.92,2179.01 2124.91,2562 2417.91,2562 2525.25,2669.34 2525.25,2761.47 MC1B.16@2559.06,2795.28
B15_L8P: MC1.54 MC1B.14 | length 1308.8
  L1-TOP w5.25: MC1.54@1720.47,2083.27 1720.47,2042.07 v1(1720.54,2042)
  L4-BOT w5.25: v1(1720.54,2042) 1730.67,2052.12 1730.67,2183.67 2120.25,2573.25 2413.25,2573.25 2514,2674 2514,2761.59 MC1B.14@2480.32,2795.28
B15_L9N: MC1.43 MC1B.3 | length 746.2
  L1-TOP w5.25: MC1.43@1562.99,2326.18 1562.99,2345.01 1553,2355 1553,2393 1816,2656 2039,2656 2052.87,2669.87 2052.87,2682.79 MC1B.3@2086.61,2716.54
B15_L9P: MC1.41 MC1B.1 | length 746.3
  L1-TOP w5.25: MC1.41@1531.5,2326.18 1531.5,2344.75 1541.75,2355 1541.75,2397.66 1795.09,2651 1811.34,2667.25 2034.34,2667.25 2041.62,2674.53 2041.62,2682.79 MC1B.1@2007.87,2716.54
B15_L10N: MC1.48 MC1B.8 | length 1146.2
  L1-TOP w5.25: MC1.48@1625.98,2083.27 1625.98,2042.07 v1(1626.06,2042)
  L4-BOT w5.25: v1(1626.06,2042) 1615.93,2052.12 1615.93,2206.02 2032.91,2623 2181.91,2623 2210.25,2651.34 2210.25,2761.43 MC1B.8@2244.1,2795.28
B15_L10P: MC1.46 MC1B.6 | length 1146.2
  L1-TOP w5.25: MC1.46@1594.49,2083.27 1594.49,2042.07 v1(1594.56,2042)
  L4-BOT w5.25: v1(1594.56,2042) 1604.68,2052.12 1604.68,2210.68 2028.25,2634.25 2177.25,2634.25 2199,2656 2199,2761.63 MC1B.6@2165.35,2795.28
B15_L11N: MC1.37 MC1A.37 | length 475.7
  L1-TOP w5.25: MC1.37@1468.5,2326.18 1468.5,2343.5 1458,2354 1458,2457.09 1619.8,2618.89 1619.8,2682.79 MC1A.37@1653.54,2716.54
B15_L11P: MC1.35 MC1A.35 | length 475.4
  L1-TOP w5.25: MC1.35@1437.01,2326.18 1437.01,2344.26 1446.75,2354 1446.75,2461.75 1608.55,2623.55 1608.55,2682.79 MC1A.35@1574.8,2716.54
B15_L12N_MRCC: MC1.51 MC1B.11 | length 943.3
  L1-TOP w5.25: MC1.51@1688.98,2326.18 1688.98,2345.02 1679,2355 1679,2376 1897,2594 2322.91,2594 2367.83,2638.92 2367.83,2682.79 MC1B.11@2401.58,2716.54
B15_L12P_MRCC: MC1.49 MC1B.9 | length 943.4
  L1-TOP w5.25: MC1.49@1657.48,2326.18 1657.48,2344.73 1667.75,2355 1667.75,2380.66 1836.09,2549 1892.34,2605.25 2318.25,2605.25 2356.58,2643.58 2356.58,2682.79 MC1B.9@2322.84,2716.54
B15_L13N_MRCC: MC1.69 MC1B.29 | length 1354.6
  L1-TOP w5.25: MC1.69@1972.44,2326.18 1972.44,2345.56 1963,2355 1963,2375 2051,2463 2731,2463 2866.75,2598.75 3014.9,2598.75 3076.49,2660.34 3076.49,2682.79 MC1B.29@3110.24,2716.54
B15_L13P_MRCC: MC1.67 MC1B.27 | length 1355.2
  L1-TOP w5.25: MC1.67@1940.95,2326.18 1940.95,2344.2 1951.75,2355 1951.75,2379.66 1989.09,2417 2046.34,2474.25 2726.34,2474.25 2862.09,2610 3010.24,2610 3065.24,2665 3065.24,2682.79 MC1B.27@3031.5,2716.54
B15_L14N: MC1.29 MC1A.29 | length 419.9
  L1-TOP w5.25: MC1A.29@1338.58,2716.54 1304.84,2682.79 1304.84,2513.16 1332.25,2485.75 1332.25,2355 1342.52,2344.73 MC1.29@1342.52,2326.18
B15_L14P: MC1.27 MC1A.27 | length 419.8
  L1-TOP w5.25: MC1A.27@1259.84,2716.54 1293.59,2682.79 1293.59,2508.5 1321,2481.09 1321,2355 1311.02,2345.02 MC1.27@1311.02,2326.18
B15_L15N: MC1.52 MC1B.12 | length 1218.1
  L1-TOP w5.25: MC1.52@1688.98,2083.27 1688.98,2042.07 v1(1689.05,2042)
  L4-BOT w5.25: v1(1689.05,2042) 1679,2052.05 1679,2186.09 2083.91,2591 2288.91,2591 2367.83,2669.92 2367.83,2761.53 MC1B.12@2401.58,2795.28
B15_L15P: MC1.50 MC1B.10 | length 1218.2
  L1-TOP w5.25: MC1.50@1657.48,2083.27 1657.48,2042.07 v1(1657.55,2042)
  L4-BOT w5.25: v1(1657.55,2042) 1667.75,2052.2 1667.75,2190.75 2079.25,2602.25 2284.25,2602.25 2356.58,2674.58 2356.58,2761.53 MC1B.10@2322.84,2795.28
B15_L16N: MC1.38 MC1A.38 | length 879.6
  L1-TOP w5.25: MC1.38@1468.5,2083.27 1468.5,2042.07 v1(1468.58,2042)
  L4-BOT w5.25: v1(1468.58,2042) 1458.45,2052.12 1458.45,2376.45 1620.25,2538.25 1620.25,2761.98 MC1A.38@1653.54,2795.28
B15_L16P: MC1.36 MC1A.36 | length 880
  L1-TOP w5.25: MC1.36@1437.01,2083.27 1437.01,2042.07 v1(1437.08,2042)
  L4-BOT w5.25: v1(1437.08,2042) 1447.2,2052.12 1447.2,2381.11 1609,2542.91 1609,2761.08 MC1A.36@1574.8,2795.28
B15_L17N: MC1.33 MC1A.33 | length 436.6
  L1-TOP w5.25: MC1.33@1405.51,2326.18 1405.51,2344.49 1395,2355 1395,2512.09 1462.32,2579.41 1462.32,2682.79 MC1A.33@1496.06,2716.54
B15_L17P: MC1.31 MC1A.31 | length 436.2
  L1-TOP w5.25: MC1.31@1374.02,2326.18 1374.02,2345.27 1383.75,2355 1383.75,2516.75 1451.07,2584.07 1451.07,2682.79 MC1A.31@1417.32,2716.54
B15_L18N: MC1.25 MC1A.25 | length 459.1
  L1-TOP w5.25: MC1A.25@1181.1,2716.54 1147.36,2682.79 1147.36,2621.64 1269.25,2499.75 1269.25,2355 1279.53,2344.72 MC1.25@1279.53,2326.18
B15_L18P: MC1.23 MC1A.23 | length 458.9
  L1-TOP w5.25: MC1A.23@1102.36,2716.54 1136.11,2682.79 1136.11,2616.98 1258,2495.09 1258,2355 1248.03,2345.03 MC1.23@1248.03,2326.18
B15_L19N: MC1.18 MC1A.18 | length 941.6
  L1-TOP w5.25: MC1.18@1153.54,2083.27 1153.54,2042.07 v1(1153.62,2042)
  L4-BOT w5.25: MC1A.18@866.14,2795.28 832.4,2761.53 832.4,2687.6 1144.25,2375.75 1144.25,2051.37 v1(1153.62,2042)
B15_L19P: MC1.16 MC1A.16 | length 942.2
  L1-TOP w5.25: MC1.16@1122.05,2083.27 1122.05,2042.07 v1(1122.12,2042)
  L4-BOT w5.25: MC1A.16@787.4,2795.28 821.15,2761.53 821.15,2682.94 1133,2371.09 1133,2052.88 v1(1122.12,2042)
B15_L20N: MC1.34 MC1A.34 | length 840.8
  L1-TOP w5.25: MC1.34@1405.51,2083.27 1405.51,2042.07 v1(1405.58,2042)
  L4-BOT w5.25: v1(1405.58,2042) 1395,2052.58 1395,2413.09 1462.32,2480.41 1462.32,2761.53 MC1A.34@1496.06,2795.28
B15_L20P: MC1.32 MC1A.32 | length 840.4
  L1-TOP w5.25: MC1.32@1374.02,2083.27 1374.02,2042.07 v1(1374.09,2042)
  L4-BOT w5.25: v1(1374.09,2042) 1383.75,2051.66 1383.75,2417.75 1451.07,2485.07 1451.07,2761.53 MC1A.32@1417.32,2795.28
B15_L21N: MC1.17 MC1A.17 | length 595.1
  L1-TOP w5.25: MC1A.17@866.14,2716.54 832.4,2682.79 832.4,2672 844.4,2660 942.91,2660 1143.25,2459.66 1143.25,2355 1153.54,2344.71 MC1.17@1153.54,2326.18
B15_L21P: MC1.15 MC1A.15 | length 594.9
  L1-TOP w5.25: MC1A.15@787.4,2716.54 821.15,2682.79 821.15,2667.34 839.74,2648.75 938.25,2648.75 1132,2455 1132,2355 1122.05,2345.05 MC1.15@1122.05,2326.18
B15_L22N: MC1.44 MC1B.4 | length 1036.2
  L1-TOP w5.25: MC1.44@1562.99,2083.27 1562.99,2042.07 v1(1563.06,2042)
  L4-BOT w5.25: v1(1563.06,2042) 1553,2052.06 1553,2208.09 2001.91,2657 2029.91,2657 2052.87,2679.96 2052.87,2761.53 MC1B.4@2086.61,2795.28
B15_L22P: MC1.42 MC1B.2 | length 1036.2
  L1-TOP w5.25: MC1.42@1531.5,2083.27 1531.5,2042.07 v1(1531.57,2042)
  L4-BOT w5.25: v1(1531.57,2042) 1541.75,2052.18 1541.75,2212.75 1997.25,2668.25 2025.25,2668.25 2041.62,2684.62 2041.62,2761.53 MC1B.2@2007.87,2795.28
B15_L23N: MC1.26 MC1A.26 | length 863.3
  L1-TOP w5.25: MC1.26@1279.53,2083.27 1279.53,2042.07 v1(1279.6,2042)
  L4-BOT w5.25: MC1A.26@1181.1,2795.28 1147.36,2761.53 1147.36,2632.64 1269.25,2510.75 1269.25,2052.35 v1(1279.6,2042)
B15_L23P: MC1.24 MC1A.24 | length 863.1
  L1-TOP w5.25: MC1.24@1248.03,2083.27 1248.03,2042.07 v1(1248.1,2042)
  L4-BOT w5.25: MC1A.24@1102.36,2795.28 1136.11,2761.53 1136.11,2627.98 1258,2506.09 1258,2051.9 v1(1248.1,2042)
B15_L24N: MC1.30 MC1A.30 | length 824.1
  L1-TOP w5.25: MC1.30@1342.52,2083.27 1342.52,2042.07 v1(1342.59,2042)
  L4-BOT w5.25: MC1A.30@1338.58,2795.28 1305,2761.69 1305,2618.91 1332.47,2591.44 1332.47,2052.12 v1(1342.59,2042)
B15_L24P: MC1.28 MC1A.28 | length 824.2
  L1-TOP w5.25: MC1.28@1311.02,2083.27 1311.02,2042.07 v1(1311.1,2042)
  L4-BOT w5.25: MC1A.28@1259.84,2795.28 1293.75,2761.37 1293.75,2614.25 1321.22,2586.78 1321.22,2052.12 v1(1311.1,2042)
B16_L6N: MC2.67 MC2B.27 | length 1566.7
  L1-TOP w8: MC2.67@1940.95,1066.34 v1(1940.95,1108)
  L4-BOT w6: v1(1940.95,1108) 1940.95,1073.05 2065,949 2309,949 2347,987 2519,987 2992,514 2992,393.83 MC2B.27@3031.5,354.33
B16_L11N: MC2.63 MC2B.23 | length 1441.2
  L1-TOP w5.25: MC2.63@1877.95,1066.34 v1(1877.95,1108)
  L4-BOT w5.25: v1(1877.95,1108) 1867.83,1097.88 1867.83,1058.17 2010,916 2159.91,916 2479.91,596 2713.91,596 2839.74,470.17 2839.74,388.61 MC2B.23@2874.02,354.33
B16_L11P: MC2.61 MC2B.21 | length 1440.7
  L1-TOP w5.25: MC2.61@1846.46,1066.34 v1(1846.46,1108)
  L4-BOT w5.25: v1(1846.46,1108) 1856.58,1097.88 1856.58,1053.51 2005.34,904.75 2155.25,904.75 2475.25,584.75 2709.25,584.75 2828.49,465.51 2828.49,387.55 MC2B.21@2795.28,354.33
B16_L12N: MC2.53 MC2B.13 | length 1218.4
  L1-TOP w5.25: MC2.53@1720.47,1066.34 v1(1720.47,1108)
  L4-BOT w5.25: v1(1720.47,1108) 1710.35,1097.88 1710.35,1031.9 2076,666.25 2246.66,666.25 2348.91,564 2446.04,466.87 2446.04,388.61 MC2B.13@2480.32,354.33
B16_L12P: MC2.51 MC2B.11 | length 1218
  L1-TOP w5.25: MC2.51@1688.98,1066.34 v1(1688.98,1108)
  L4-BOT w5.25: v1(1688.98,1108) 1699.1,1097.88 1699.1,1027.24 2071.34,655 2242,655 2434.79,462.21 2434.79,387.55 MC2B.11@2401.58,354.33
B16_L13N: MC2.49 MC2B.9 | length 1150.4
  L1-TOP w5.25: MC2.49@1657.48,1066.34 v1(1657.48,1108)
  L4-BOT w5.25: v1(1657.48,1108) 1647.36,1097.88 1647.36,1013.64 1868.25,792.75 1868.25,773.33 2032.33,609.25 2153.75,609.25 2289.25,473.75 2289.25,387.92 MC2B.9@2322.84,354.33
B16_L13P: MC2.47 MC2B.7 | length 1150.6
  L1-TOP w5.25: MC2.47@1625.98,1066.34 v1(1625.98,1108)
  L4-BOT w5.25: v1(1625.98,1108) 1636.11,1097.88 1636.11,1008.98 1857,788.09 1857,768.67 2027.67,598 2149.09,598 2278,469.09 2278,388.24 MC2B.7@2244.1,354.33
B16_L14N: MC2.57 MC2B.17 | length 1288.2
  L1-TOP w5.25: MC2.57@1783.46,1066.34 v1(1783.46,1108)
  L4-BOT w5.25: v1(1783.46,1108) 1773.34,1097.88 1773.34,1083.66 2036,821 2190.82,821 2482.82,529 2550.91,529 2604.25,475.66 2604.25,387.88 MC2B.17@2637.8,354.33
B16_L14P: MC2.55 MC2B.15 | length 1288.3
  L1-TOP w5.25: MC2.55@1751.97,1066.34 v1(1751.97,1108)
  L4-BOT w5.25: v1(1751.97,1108) 1762.09,1097.88 1762.09,1079 2031.34,809.75 2186.16,809.75 2478.16,517.75 2546.25,517.75 2593,471 2593,388.28 MC2B.15@2559.06,354.33
B16_L19N: MC2.65 MC2B.25 | length 1474.7
  L1-TOP w8: MC2.65@1909.45,1066.34 v1(1909.45,1108)
  L4-BOT w8: v1(1909.45,1108) 1909.45,1060.55 2037,933 2174,933 2445,662 2730,662 2912,480 2912,395.09 MC2B.25@2952.76,354.33
B34_IO_0: MC2.68 MC2B.28 | length 1304.3
  L1-TOP w6: MC2.68@1940.95,823.43 1940.95,776.05 2042,675 2831,675 3031.5,474.5 MC2B.28@3031.5,433.07
B34_IO_25: MC2.66 MC2B.26 | length 1273
  L1-TOP w6: MC2.66@1909.45,823.43 1909.45,780.55 2036,654 2805,654 2952.76,506.24 MC2B.26@2952.76,433.07
B34_L1N: MC2.50 MC2B.10 | length 895.4
  L1-TOP w5.25: MC2.50@1657.48,823.43 1657.48,801.48 1648,792 1648,762.36 1879.36,531 2255.91,531 2286.25,500.66 2286.25,468 2321.18,433.07 MC2B.10@2322.84,433.07
B34_L1P: MC2.48 MC2B.8 | length 892.6
  L1-TOP w5.25: MC2.48@1625.98,823.43 1625.98,802.77 1636.75,792 1636.75,757.7 1874.7,519.75 2251.25,519.75 2275,496 2275,463.98 MC2B.8@2244.1,433.07
B34_L2N: MC2.64 MC2B.24 | length 1257.8
  L1-TOP w5.25: MC2.64@1877.95,823.43 1877.95,802.95 1867,792 1867,780.91 2013.91,634 2774.91,634 2840.27,568.64 2840.27,466.82 MC2B.24@2874.02,433.07
B34_L2P: MC2.62 MC2B.22 | length 1257.1
  L1-TOP w5.25: MC2.62@1846.46,823.43 1846.46,801.29 1855.75,792 1855.75,776.25 2009.25,622.75 2770.25,622.75 2829.02,563.98 2829.02,466.82 MC2B.22@2795.28,433.07
B34_L3N: MC2.54 MC2B.14 | length 999.6
  L1-TOP w5.25: MC2.54@1720.47,823.43 1720.47,804.47 1710,794 1710,765 1908,567 2395.91,567 2446.25,516.66 2446.25,467.14 MC2B.14@2480.32,433.07
B34_L3P: MC2.52 MC2B.12 | length 999
  L1-TOP w5.25: MC2.52@1688.98,823.43 1688.98,803.77 1698.75,794 1698.75,760.34 1839.34,619.75 1903.34,555.75 2391.25,555.75 2435,512 2435,466.5 MC2B.12@2401.58,433.07
B34_L4N: MC2.34 MC2A.34 | length 440.3
  L1-TOP w5.25: MC2.34@1405.51,823.43 1405.51,804.12 1395.39,794 1395.39,709.61 1462.25,642.75 1462.25,460 1489.18,433.07 MC2A.34@1496.06,433.07
B34_L4P: MC2.32 MC2A.32 | length 440.1
  L1-TOP w5.25: MC2.32@1374.02,823.43 1374.02,804.12 1384.14,794 1384.14,704.95 1451,638.09 1451,460 1424.07,433.07 MC2A.32@1417.32,433.07
B34_L5N: MC2.58 MC2B.18 | length 1081
  L1-TOP w5.25: MC2.58@1783.46,823.43 1783.46,803.47 1773,793 1773,766.34 1938.34,601 2496.91,601 2604.25,493.66 2604.25,465 2636.18,433.07 MC2B.18@2637.8,433.07
B34_L5P: MC2.56 MC2B.16 | length 1081.2
  L1-TOP w5.25: MC2.56@1751.97,823.43 1751.97,802.78 1761.75,793 1761.75,761.68 1933.68,589.75 2492.25,589.75 2593,489 2593,465 2561.07,433.07 MC2B.16@2559.06,433.07
B34_L6N: MC2.33 MC2A.33 | length 841.6
  L1-TOP w5.25: MC2.33@1405.51,1066.34 v1(1405.51,1108)
  L4-BOT w5.25: v1(1405.51,1108) 1395.39,1097.88 1395.39,702.61 1463.25,634.75 1463.25,447.23 1462.85,446.83 1462.85,387.55 MC2A.33@1496.06,354.33
B34_L6P: MC2.31 MC2A.31 | length 842
  L1-TOP w5.25: MC2.31@1374.02,1066.34 v1(1374.02,1108)
  L4-BOT w5.25: v1(1374.02,1108) 1384.14,1097.88 1384.14,697.95 1452,630.09 1452,451.89 1451.6,451.49 1451.6,388.61 MC2A.31@1417.32,354.33
B34_L7N: MC2.45 MC2B.5 | length 1112.8
  L1-TOP w5.25: MC2.45@1594.49,1066.34 v1(1594.49,1108)
  L4-BOT w5.25: v1(1594.49,1108) 1584.37,1097.88 1584.37,997.63 1765.25,816.75 1765.25,716.85 1811.1,671 ; 1817,671 1811.1,671 ; MC2B.5@2165.35,354.33 2131.25,388.44 2131.25,464.75 2035.75,560.25 1921.85,560.25 1811.1,671
B34_L7P: MC2.43 MC2B.3 | length 1106.6
  L1-TOP w5.25: MC2.43@1562.99,1066.34 v1(1562.99,1108)
  L4-BOT w5.25: v1(1562.99,1108) 1573.12,1097.88 1573.12,992.97 1754,812.09 1754,712.19 1917.19,549 2031.09,549 2120,460.09 2120,387.72 MC2B.3@2086.61,354.33
B34_L8N: MC2.38 MC2A.38 | length 475.7
  L1-TOP w5.25: MC2.38@1468.5,823.43 1468.5,802.5 1459,793 1459,745 1621.25,582.75 1621.25,464 1652.18,433.07 MC2A.38@1653.54,433.07
B34_L8P: MC2.36 MC2A.36 | length 479.1
  L1-TOP w5.25: MC2.36@1437.01,823.43 1437.01,803.74 1447.75,793 1447.75,740.34 1610,578.09 1610,464 1579.07,433.07 MC2A.36@1574.8,433.07
B34_L9N: MC2.37 MC2A.37 | length 880.4
  L1-TOP w5.25: MC2.37@1468.5,1066.34 v1(1468.5,1108)
  L4-BOT w5.25: v1(1468.5,1108) 1458.38,1097.88 1458.38,971.62 1620.33,809.67 1620.33,387.55 MC2A.37@1653.54,354.33
B34_L9P: MC2.35 MC2A.35 | length 880.8
  L1-TOP w5.25: MC2.35@1437.01,1066.34 v1(1437.01,1108)
  L4-BOT w5.25: v1(1437.01,1108) 1447.13,1097.88 1447.13,966.96 1609.08,805.01 1609.08,388.61 MC2A.35@1574.8,354.33
B34_L10N: MC2.46 MC2B.6 | length 789.3
  L1-TOP w5.25: MC2.46@1594.49,823.43 1594.49,803.49 1584,793 1584,764.37 1852.37,496 2114.91,496 2131.25,479.66 2131.25,467.18 MC2B.6@2165.35,433.07
B34_L10P: MC2.44 MC2B.4 | length 788.7
  L1-TOP w5.25: MC2.44@1562.99,823.43 1562.99,802.76 1572.75,793 1572.75,759.71 1847.71,484.75 2110.25,484.75 2120,475 2120,466.46 MC2B.4@2086.61,433.07
B34_L11N: MC2.26 MC2A.26 | length 457.5
  L1-TOP w5.25: MC2A.26@1181.1,433.07 1149.25,464.92 1149.25,638.19 1269.25,758.19 1269.25,795 1279.53,805.28 MC2.26@1279.53,823.43
B34_L11P: MC2.24 MC2A.24 | length 459
  L1-TOP w5.25: MC2A.24@1102.36,433.07 1138,468.71 1138,642.85 1258,762.85 1258,795 1248.03,804.97 MC2.24@1248.03,823.43
B34_L13N_MRCC: MC2.77 MC2B.37 | length 1755.1
  L1-TOP w5.25: MC2.77@2098.43,1066.34 v1(2098.43,1108)
  L4-BOT w5.25: v1(2098.43,1108) 2088.3,1097.88 2088.3,1091.61 2104.91,1075 2620.91,1075 3105.66,590.25 3275.66,590.25 3321.91,544 3390.92,474.99 3390.92,388.61 MC2B.37@3425.2,354.33
B34_L13P_MRCC: MC2.75 MC2B.35 | length 1754.7
  L1-TOP w5.25: MC2.75@2066.93,1066.34 v1(2066.93,1108)
  L4-BOT w5.25: v1(2066.93,1108) 2077.05,1097.88 2077.05,1086.95 2100.25,1063.75 2616.25,1063.75 3101,579 3271,579 3379.67,470.33 3379.67,387.55 MC2B.35@3346.46,354.33
B34_L14N: MC2.25 MC2A.25 | length 864.4
  L1-TOP w5.25: MC2.25@1279.53,1066.34 v1(1279.53,1108)
  L4-BOT w5.25: MC2A.25@1181.1,354.33 1147,388.43 1147,619.09 1223.25,695.34 1223.25,1034.19 1269.41,1080.34 1269.41,1097.88 v1(1279.53,1108)
B34_L14P: MC2.23 MC2A.23 | length 864.1
  L1-TOP w5.25: MC2.23@1248.03,1066.34 v1(1248.03,1108)
  L4-BOT w5.25: MC2A.23@1102.36,354.33 1135.75,387.72 1135.75,623.75 1212,700 1212,1038.85 1258.16,1085 1258.16,1097.88 v1(1248.03,1108)
B34_L15N: MC2.29 MC2A.29 | length 824.8
  L1-TOP w5.25: MC2.29@1342.52,1066.34 v1(1342.52,1108)
  L4-BOT w5.25: MC2A.29@1338.58,354.33 1305,387.91 1305,623.09 1332.4,650.49 1332.4,1097.88 v1(1342.52,1108)
B34_L15P: MC2.27 MC2A.27 | length 824.9
  L1-TOP w5.25: MC2.27@1311.02,1066.34 v1(1311.02,1108)
  L4-BOT w5.25: MC2A.27@1259.84,354.33 1293.75,388.24 1293.75,627.75 1321.15,655.15 1321.15,1097.88 v1(1311.02,1108)
B34_L16N: MC2.6 MC2A.6 | length 838.7
  L1-TOP w5.25: MC2A.6@393.7,433.07 386.93,433.07 359,461 359,482 616,739 921.91,739 954.25,771.34 954.25,794 964.57,804.32 MC2.6@964.57,823.43
B34_L16P: MC2.4 MC2A.4 | length 836.7
  L1-TOP w5.25: MC2A.4@314.96,433.07 319.82,433.07 347.75,461 347.75,486.66 519.09,658 611.34,750.25 917.25,750.25 943,776 943,794 933.07,803.93 MC2.4@933.07,823.43
B34_L17N: MC2.5 MC2A.5 | length 1060.2
  L1-TOP w5.25: MC2.5@964.57,1066.34 v1(964.57,1108)
  L4-BOT w5.25: MC2A.5@393.7,354.33 359.43,388.61 359.43,479.36 954.41,1074.34 954.41,1097.84 v1(964.57,1108)
B34_L17P: MC2.3 MC2A.3 | length 1059.8
  L1-TOP w5.25: v1(933,1108) MC2.3@933.07,1066.34 MC2.3@933.07,1066.34
  L4-BOT w5.25: MC2A.3@314.96,354.33 348.18,387.55 348.18,484.02 943.16,1079 943.16,1097.84 v1(933,1108)
B34_L18N: MC2.30 MC2A.30 | length 418.5
  L1-TOP w5.25: MC2A.30@1338.58,433.07 1337.93,433.07 1307,464 1307,720.09 1332.25,745.34 1332.25,794 1342.52,804.27 MC2.30@1342.52,823.43
B34_L18P: MC2.28 MC2A.28 | length 422.7
  L1-TOP w5.25: MC2A.28@1259.84,433.07 1264.82,433.07 1295.75,464 1295.75,724.75 1321,750 1321,794 1311.02,803.98 MC2.28@1311.02,823.43
B34_L19N: MC2.18 MC2A.18 | length 589.6
  L1-TOP w5.25: MC2A.18@866.14,433.07 863.93,433.07 833,464 833,531 951.75,649.75 1039.66,649.75 1143.25,753.34 1143.25,795 1153.54,805.29 MC2.18@1153.54,823.43
B34_L19P: MC2.16 MC2A.16 | length 590.7
  L1-TOP w5.25: MC2A.16@787.4,433.07 790.82,433.07 821.75,464 821.75,535.66 947.09,661 1035,661 1132,758 1132,795 1122.05,804.95 MC2.16@1122.05,823.43
B34_L20N: MC2.9 MC2A.9 | length 1020.8
  L1-TOP w5.25: MC2.9@1027.56,1066.34 v1(1027.56,1108)
  L4-BOT w5.25: MC2A.9@551.18,354.33 517.25,388.26 517.25,585.15 1017.44,1085.34 1017.44,1097.88 v1(1027.56,1108)
B34_L20P: MC2.7 MC2A.7 | length 1020.6
  L1-TOP w5.25: MC2.7@996.06,1066.34 v1(996.06,1108)
  L4-BOT w5.25: MC2A.7@472.44,354.33 506,387.89 506,589.81 1006.19,1090 1006.19,1097.88 v1(996.06,1108)
B34_L21N: MC2.10 MC2A.10 | length 755.5
  L1-TOP w5.25: MC2A.10@551.18,433.07 542.93,433.07 517,459 517,498 728,709 957.91,709 1017.25,768.34 1017.25,793 1027.56,803.31 MC2.10@1027.56,823.43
